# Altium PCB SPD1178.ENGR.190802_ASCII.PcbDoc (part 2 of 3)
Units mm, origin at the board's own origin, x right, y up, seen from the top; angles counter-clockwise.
Board outline 150 x 150 mm, 2 copper layers (Top Layer, Bottom Layer); 315 components, 164 nets, 838 pads, 882 vias.
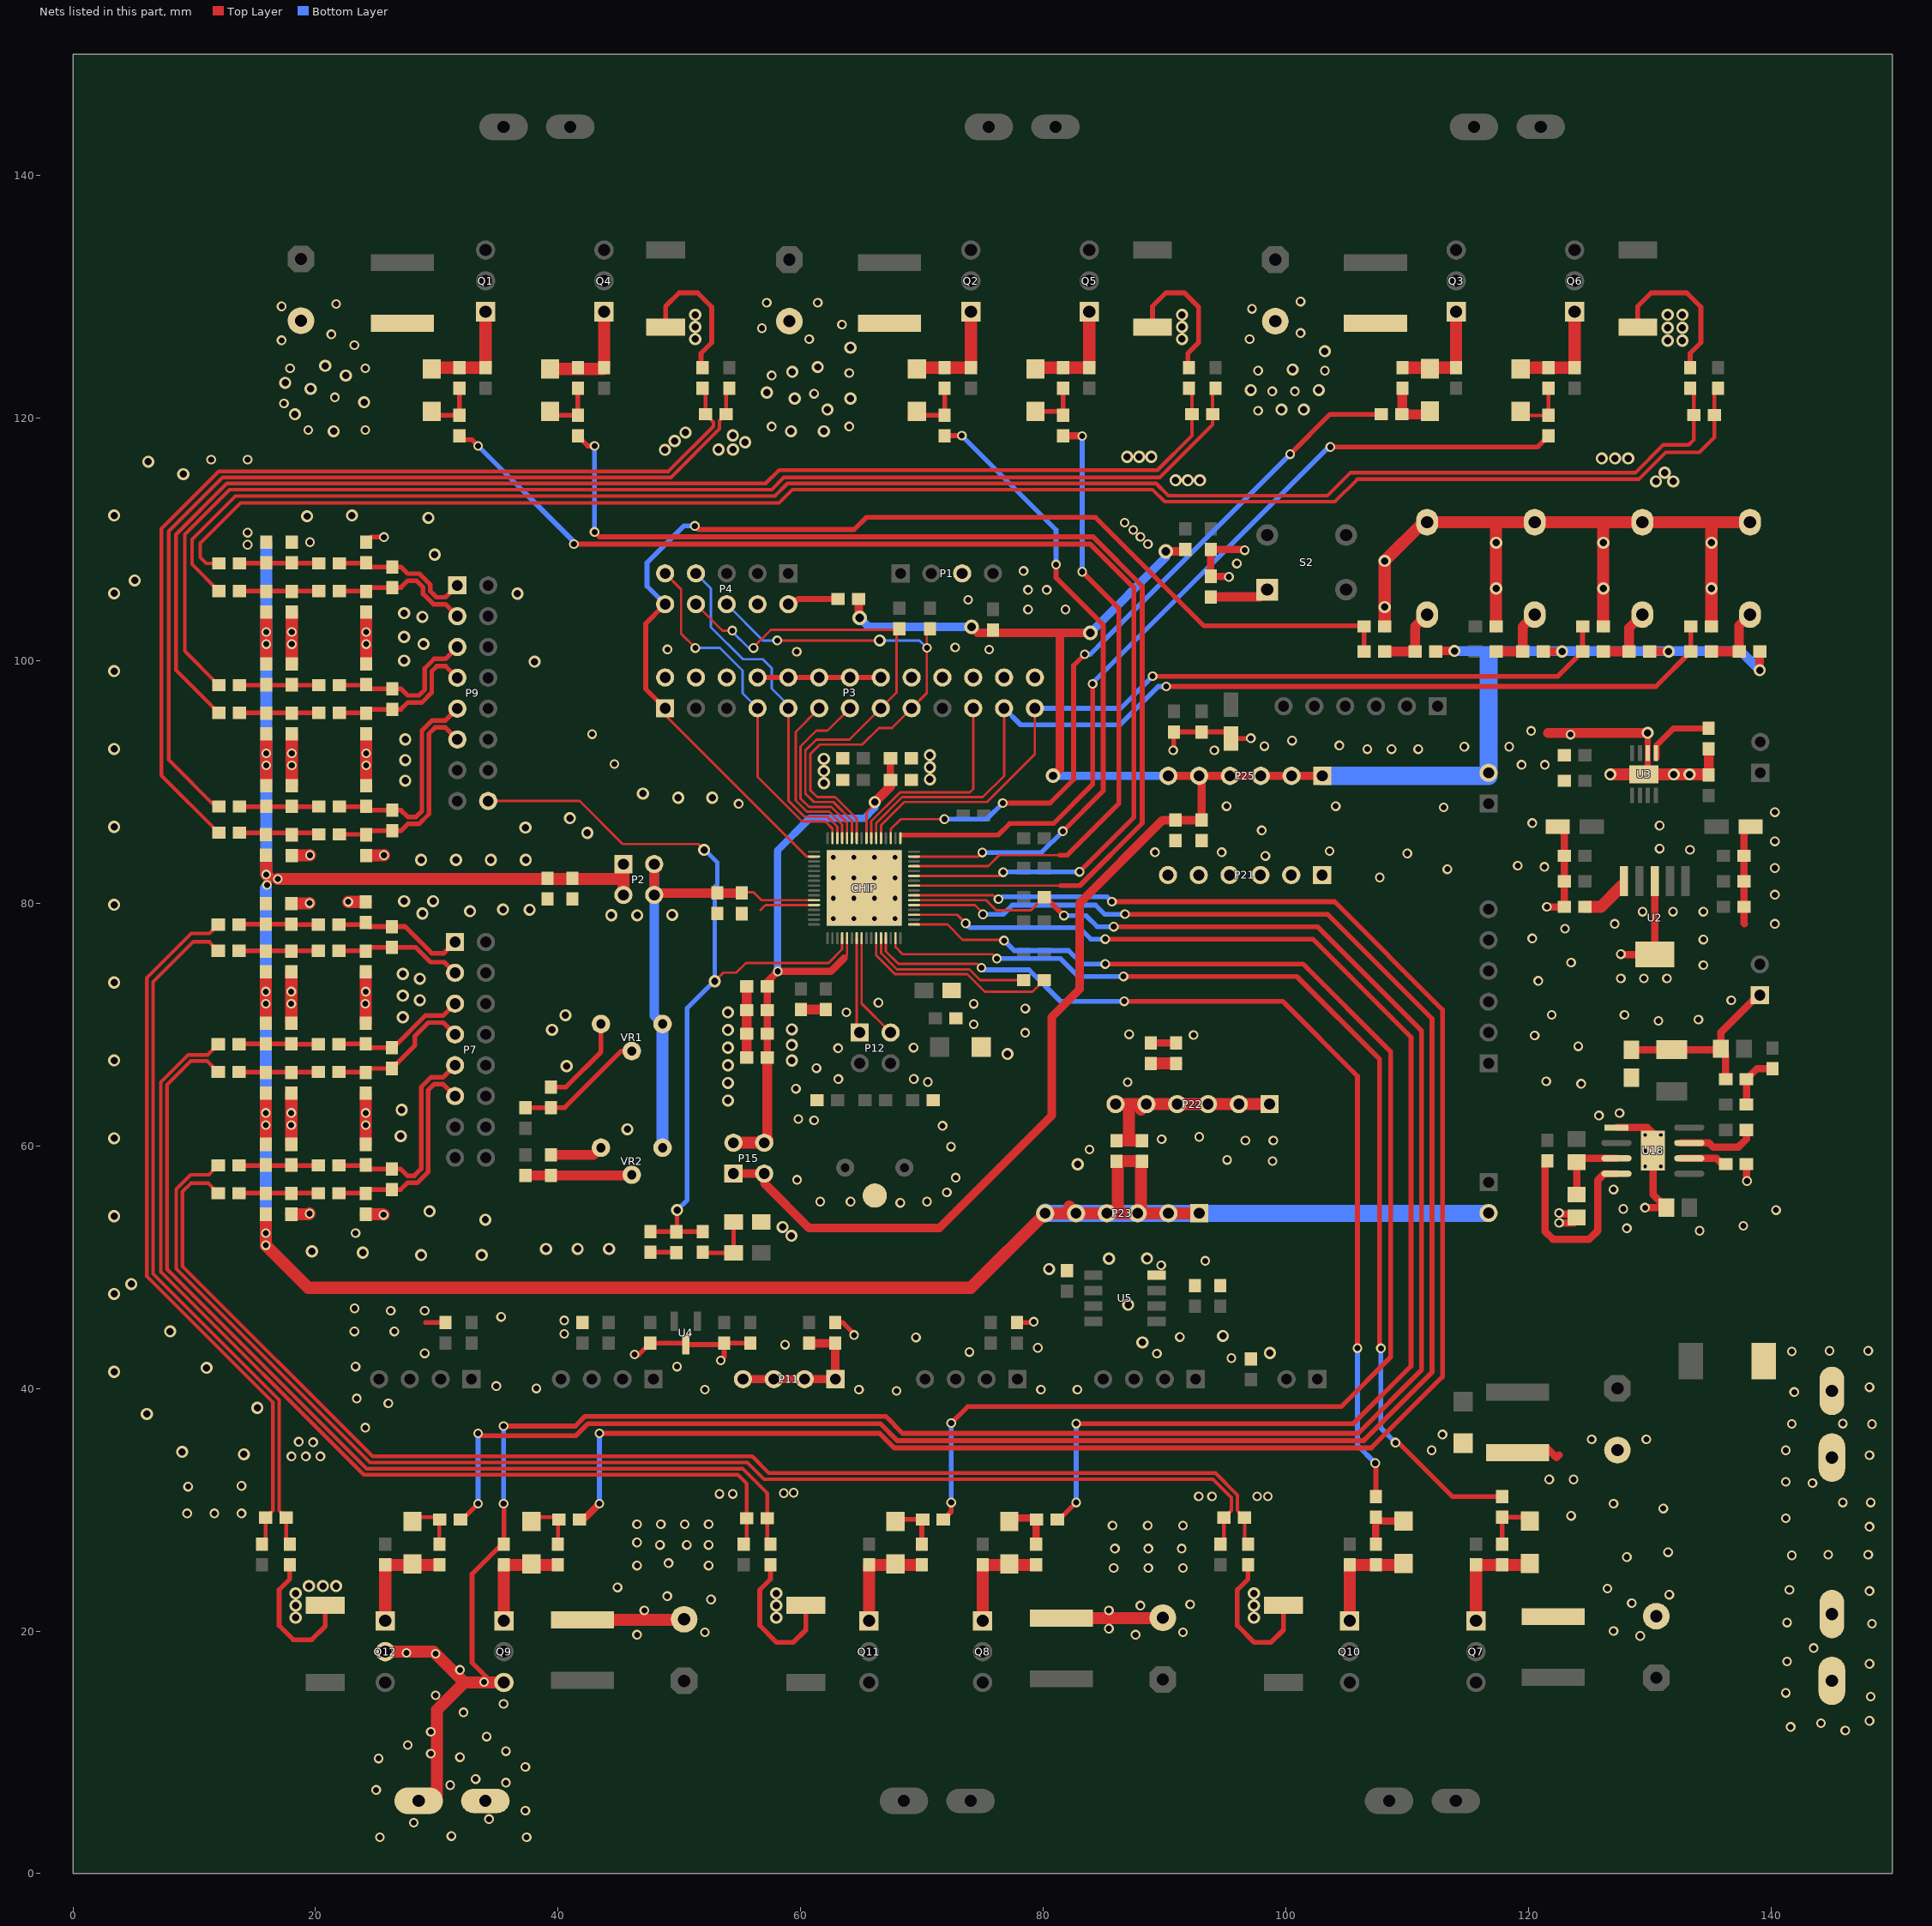
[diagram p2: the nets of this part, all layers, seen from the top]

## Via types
v1: diameter 0.8, hole 0.5, Top Layer to Bottom Layer, tented both sides, 575 vias
v2: diameter 1, hole 0.6, Top Layer to Bottom Layer, 157 vias
v3: diameter 0.8, hole 0.5, Top Layer to Bottom Layer, 69 vias
v4: diameter 1, hole 0.6, Top Layer to Bottom Layer, tented both sides, 52 vias
v5: diameter 0.8, hole 0.4, Top Layer to Bottom Layer, 16 vias
v6: diameter 1.2, hole 0.7, Top Layer to Bottom Layer, tented both sides, 7 vias
v7: diameter 0.5, hole 0.3, Top Layer to Bottom Layer, 6 vias

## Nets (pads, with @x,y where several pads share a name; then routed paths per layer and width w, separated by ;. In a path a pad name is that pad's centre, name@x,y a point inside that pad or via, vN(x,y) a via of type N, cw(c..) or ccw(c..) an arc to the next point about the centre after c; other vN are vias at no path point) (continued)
ADC15: CHIP.20 CL420.2 P9.16 R442.1 R443.1 | length 69.7
  Top Layer w0.2: P9.16@34.232,88.42 41.78,88.42 45.32,84.88 51.55,84.88 v4(52.03,84.4) ; v4(52.91,73.57) 53.62,74.28 54.68,74.28 55.48,75.08 62.29,75.08 63.413,76.203 CHIP.20@63.413,77.117
  Top Layer w0.381: CL420.2@47.608,52.92 R443.1@49.767,52.92 ; v4(49.8,54.7) 49.8,52.953 R443.1@49.767,52.92 ; R442.1@51.926,52.92 R443.1@49.767,52.92
  Bottom Layer w0.381: v4(49.8,54.7) 50.64,55.54 50.64,71.35 v4@52.91,73.62 ; v4(52.03,84.4) 52.08,84.4 53.121,83.359 53.121,81.54 52.91,81.329 v4@52.91,73.62 ; v4(52.91,73.57) v4@52.91,73.62
AGND: C90.1 C91.1 C132.2 C133.2 C142.2 C143.2 C152.2 C153.2 C162.2 C163.2 C172.2 C173.2 C182.2 C183.2 C232.2 C233.1 C234.2 C235.1 C236.2 C237.1 C238.2 C239.1 C240.2 C241.1 C242.2 C243.1 CB8.1 CB9.1 CB10.1 CF3.2 CF4.2 CHIP.12 CL1.1 CL2.1 CL4.2 CL5.2 CL6.2 CL13.1 CL14.1 CL27.1 CL28.1 CL29.1 CL38.1 CL39.1 CL420.1 P22.1 P22.2 P22.3 P22.4 P22.5 P22.6 R41.1 R43.1 R443.2 U4.3 U5.4 VR1.3 VR2.3 | length 100.1
  Top Layer w0.2: 56.67,79.43 57.087,79.847 CHIP.12@61.094,79.847
  Top Layer w0.4: C153.2@24.172,109.756 24.592,110.176 v1(25.642,110.176) ; 29.073,45.427 CL5.2@30.701,45.427 ; C90.1@39.4,64.85 40.65,64.85 43.528,67.728 VR1.3@43.528,70.044 ; v1(46.3,42.8) 46.665,42.8 CB9.1@47.592,43.727 50.403,43.727 U4.3@50.513,43.617 53.578,43.617 CL29.1@53.688,43.727 ; CL420.1@47.608,51.22 R443.2@49.767,51.22 ; v1(53.4,42.3) 53.688,42.588 CL29.1@53.688,43.727 ; CB8.1@55.847,43.727 CL29.1@53.688,43.727 ; CL6.2@62.832,45.427 63.473,45.427 64.4,44.5 v1(64.4,44.4) ; CL4.2@77.818,45.427 79.127,45.427 v1(79.2,45.5)
  Top Layer w0.8: C91.1@39.4,59.25 42.934,59.25 VR2.3@43.528,59.844
  Top Layer w1: C238.2@18.004,54.358 19.45,54.358 v1(19.504,54.412) ; C239.1@18.004,60.122 v1(18.004,61.712) v1(18.004,62.712) C240.2@18.004,64.345 ; C241.1@18.004,70.109 v1(18.004,71.712) v1(18.004,72.712) C242.2@18.004,74.34 ; C243.1@18.029,79.977 19.469,79.977 v1(19.504,80.012) ; C232.2@18.042,83.937 19.519,83.937 v1(19.542,83.96) ; C233.1@18.042,89.701 v1(18.042,91.36) v1(18.042,92.36) C234.2@18.042,93.951 ; C235.1@18.042,99.71 v1(18.042,101.36) v1(18.042,102.36) C236.2@18.042,103.992 ; v1(22.704,80.112) 22.712,80.104 C183.2@24.134,80.104 ; C162.2@24.134,54.358 25.558,54.358 v1(25.604,54.312) ; C163.2@24.134,60.122 v1(24.134,61.712) v1(24.134,62.712) C172.2@24.134,64.345 ; C173.2@24.134,70.109 v1(24.134,72.712) C182.2@24.134,74.34 ; C132.2@24.172,83.937 25.619,83.937 v1(25.642,83.96) ; C133.2@24.172,89.701 v1(24.172,91.36) v1(24.172,92.36) C142.2@24.172,93.951 ; C143.2@24.172,99.715 v1(24.172,101.36) v1(24.172,102.36) C152.2@24.172,103.992 ; P22.6@85.95,63.44 P22.5@88.49,63.44 ; CF4.2@86.03,60.43 87.13,60.43 CF3.2@88.13,60.43 ; 87.05,60.43 87.05,63 ; P22.5@88.05,63 P22.5@88.49,63.44 ; R43.1@88.85,66.79 R41.1@90.95,66.79 ; P22.1@98.65,63.44 P22.2@96.11,63.44 P22.3@93.57,63.44 P22.4@91.03,63.44 P22.5@88.49,63.44
  other v1: 67.9,39.8 52.1,39.9 64.8,39.9 79.8,39.9 82.8,39.9 38.2,40 34.9,40.2 23.3,41.8 49.8,41.8 95.5,42.5 89.36,42.87 29,42.9 73.9,43 79.54,43.35 58.7,43.6 69.5,44.2 91.25,44.24 40.5,44.5 40.5,45.6 35.3,45.9 29,46.4 89.71,50.15 93.35,50.52 23.3,52.8 98.89,58.74 95.15,58.84 83.8,59.69 96.65,60.44 98.95,60.44 89.75,60.54 92.85,60.74 86.95,65.24 24.104,71.712 19.542,109.76
  other v2: 14.1,34.567 9,34.767 6.1,37.9 15.2,38.4 3.4,41.367 11.016,41.7 98.67,42.92 88.17,43.8 94.8,44.33 8.016,44.7 3.4,47.785 4.816,48.6 80.47,49.84 85.41,50.7 88.54,50.71 28.7,51 33.7,51 23.9,51.2 19.7,51.3 39,51.5 41.6,51.5 44.2,51.5 34,53.9 3.4,54.204 29.4,54.6 82.83,58.48 3.4,60.622 27.016,60.8 45.7,61.367 27.1,62.967 40.7,66.567 3.4,67.04 39.5,69.567 27.2,70.6 40.6,70.767 28.6,72 27.2,72.384 3.4,73.458 28.6,73.767 27.2,74.167 46.52,79 44.39,79.01 49.41,79.03 28.81,79.15 32.73,79.34 35.45,79.48 37.65,79.46 3.4,79.876 27.3,80.167 29.7,80.167 28.7,83.567 31.577,83.567 34.453,83.567 37.33,83.567 42.41,85.8 37.3,86.23 3.4,86.295 40.97,87.01 49.9,88.7 52.7,88.7 46.99,89.04 27.4,90.1 27.4,91.8 3.4,92.713 27.4,93.5 3.4,99.131 38.06,99.91 27.3,100 28.9,101.367 27.3,101.95 28.816,103.6 27.3,103.9 36.65,105.52 3.4,105.549 5.1,106.6 29.82,108.74 29.3,111.767 19.3,111.9 3.4,111.967 23,111.967 130.5,114.767 131.92,114.767 90.9,114.867 91.9,114.867 92.9,114.867 9.1,115.367 131.216,115.483 6.216,116.4 126.03,116.66 127.123,116.66 128.216,116.66 86.9,116.8 87.9,116.8 88.9,116.8 48.8,117.367 53.216,117.4 54.416,117.4 55.416,118 49.6,118.1 54.4,118.567 50.5,118.8
  other v3: 9.416,29.7 11.658,29.7 13.9,29.7 92.8,31.1 93.9,31.1 97.616,31.1 98.5,31.1 53.3,31.3 54.4,31.3 58.6,31.367 59.416,31.4 9.5,31.9 13.9,31.967 18.016,34.4 19.2,34.4 20.4,34.4 19.8,35.567 18.616,35.6 24.1,36.767 26,38.767 23.4,39.167 23.2,44.7 26.5,44.7 26.2,46.4 23.216,46.6 54.88,88.19 44.64,91.47 42.8,93.93 11.4,116.567 14.4,116.567
  other v4: 86.99,46.9
ATEST: CL6.1 P11.1 P11.2 P11.3 P11.4 R34.1 | length 12.7
  Top Layer w0.7: P11.4@55.237,40.767 P11.3@57.777,40.767 P11.2@60.317,40.767 P11.1@62.857,40.767 62.832,40.792 CL6.1@62.832,43.727 R34.1@60.673,43.727
AVDD: CHIP.11 CL1.2 CL2.2 P2.2 P2.4 VR1.1 VR2.1 | length 39.9
  Top Layer w0.2: CL1.2@55.063,80.907 56.113,80.907 56.773,80.247 CHIP.11@61.094,80.247
  Top Layer w0.6: P2.2@47.92,83.22 P2.2@48.077,83.063
  Top Layer w0.8: P2.2@48.077,83.063 47.92,82.906 P2.4@47.92,80.68 48.077,80.837 CL1.2@55.133,80.837
  Bottom Layer w0.8: P2.2@47.92,83.22 P2.4@47.92,80.68 47.92,70.732 VR1.1@48.608,70.044
  Bottom Layer w1: VR2.1@48.608,59.844 VR1.1@48.608,70.044
AVDD_3V3: CF3.1 CF4.1 CL27.2 CL28.2 P2.1 P2.3 P23.1 P23.2 P23.3 P23.4 P23.5 P23.6 P27.2 R130.2 R131.2 R140.2 R141.2 R150.2 R151.2 R160.2 R161.2 R170.2 R171.2 R180.2 R181.2 | length 236.3
  Top Layer w1: R160.2@15.904,54.358 15.9,54.354 v1(15.9,51.8) 19.4,48.3 74.01,48.3 P23.6@80.15,54.44 P23.6@80.05,54.54 ; R161.2@15.904,60.122 v1(15.904,61.712) v1(15.904,62.712) R170.2@15.904,64.345 ; R171.2@15.904,70.109 v1(15.904,71.712) v1(15.904,72.712) R180.2@15.904,74.34 ; R130.2@15.942,83.937 v1(15.942,82.36) v1@16.142,82.16 ; R131.2@15.942,89.701 v1(15.942,91.36) v1(15.942,92.36) R140.2@15.942,93.951 ; R141.2@15.942,99.71 v1(15.942,101.36) v1(15.942,102.36) R150.2@15.942,103.992 ; v1(16.9,82) 45.38,82 ; P2.3@45.38,80.68 45.38,82 ; P2.1@45.38,83.22 45.38,82 ; 45.39,82 45.38,82 ; P23.6@80.2,54.44 P23.4@85.23,54.44 ; 82.15,54.98 P23.5@82.69,54.44 ; CF4.1@86.03,58.73 CF3.1@88.13,58.73 ; CF4.1@86.13,58.63 86.13,54.44 P23.3@87.77,54.44 P23.2@90.31,54.44 P23.1@92.85,54.44 ; P23.3@88.05,54.98 CF3.1@88.05,58.73
  Bottom Layer w1: v1(15.9,51.8) 15.904,51.804 v1(15.904,52.8) v1(15.904,61.712) v1@15.904,62.412 ; v1(15.904,62.712) v1(15.904,71.712) v1(15.904,72.712) v1@15.904,81.212 ; v1(15.942,82.36) v1(15.942,91.36) v1(15.942,92.36) v1(15.942,101.36) ; v1@15.942,101.46 v1(15.942,102.36) 15.942,109.65
  Bottom Layer w1.4: P23.6@80.15,54.44 P23.5@82.69,54.44 P23.4@85.23,54.44 P23.3@87.77,54.44 P23.2@90.31,54.44 P23.1@92.85,54.44 116.68,54.44 P27.2@116.7,54.46 ; P23.6@80.15,54.542 P23.6@80.201,54.491
  other v1: 16,81.5 14.4,109.55 14.4,110.55
BUCK_OUT_5V: C54.1 C55.2 L1.2 P17.1 R53.1 | length 15.3
  Top Layer w0.6: C54.1@128.18,67.953 128.204,67.929 L1.2@132.3,67.929 ; L1.2@132.6,67.929 R53.1@135.621,67.929 ; C55.2@136.25,65.8 136.25,67.6 R53.1@135.85,68 135.85,69.35 138.921,72.421 P17.1@139.06,72.421
CFBOT: CHIP.27 CL34.2 | length 16.9
  Top Layer w0.2: CHIP.27@66.213,77.117 66.213,75.706 67.77,74.149 73.731,74.149 75.18,72.7 79.105,72.7 CL34.2@80.065,73.66
CFTOP: CHIP.28 CL34.1 | length 13.9
  Top Layer w0.2: CHIP.28@66.613,77.117 66.613,75.871 67.935,74.549 73.897,74.549 74.786,73.66 CL34.1@78.365,73.66
DVDD: CHIP.21 CHIP.56 CL15.2 CL16.2 CL17.2 CL20.2 CL35.2 CL36.2 P15.2 P15.4 | length 52
  Top Layer w0.2: 63.569,75.471 63.813,75.714 CHIP.21@63.813,77.117 ; CHIP.56@65.413,85.367 65.413,87.513 v4@66.165,88.265
  Top Layer w0.6: CL17.2@57.25,67.28 CL20.2@57.25,69.235 CL36.2@57.25,71.19 CL35.2@57.25,73.145 57.25,73.53 v1(58.1,74.38) 62.479,74.38 63.569,75.471 ; 67.4,89.63 CL16.2@67.4,90.16 CL15.2@67.4,91.95
  Top Layer w0.8: P15.4@57.25,60.51 CL17.2@57.25,67.21 ; v4(66.1,88.33) 67.4,89.63
  Top Layer w1: P15.2@54.45,60.252 56.992,60.252 P15.4@57.25,60.51
  Bottom Layer w0.6: v1(58.1,74.38) 58.1,84.363 60.737,87 65.24,87 66.1,87.86 v4(66.1,88.33)
DVDD_3V3: CF5.1 CF6.1 P15.1 P15.3 P25.1 P25.2 P25.3 P25.4 P25.5 P25.6 P28.2 R32.1 R33.1 R39.1 R62.2 R63.2 R68.2 R77.1 | length 189.8
  Top Layer w0.7: P15.1@54.753,57.712 57.293,57.712 P15.3@57.293,57.405 ; P15.3@56.99,57.71 56.99,56.92 60.67,53.24 71.43,53.24 80.69,62.5 80.69,70.62 82.98,72.91 82.98,80.005 89.828,86.853 CF5.1@90.883,86.853 CF6.1@93.042,86.853 93.042,90.298 P25.5@92.84,90.5 ; R68.2@64.78,105.08 64.78,103.6 v6(64.85,103.53) ; v6(74.08,102.79) 74.59,102.28 R62.2@75.845,102.28 ; R62.2@75.845,102.528 R62.2@75.845,102.28 ; v6(80.8,90.5) 81.36,91.06 81.36,102.19 ; v6(83.86,102.28) R62.2@75.845,102.28 ; v6(90.1,109) 91.55,109 R63.2@91.7,109.15 ; P25.6@90.3,90.5 P25.5@92.84,90.5 ; P25.1@103,90.5 P25.2@100.46,90.5 P25.3@97.92,90.5 P25.4@95.38,90.5 P25.5@92.84,90.5 ; R77.1@112.35,100.75 112.39,100.79 v4(113.89,100.79) ; R32.1@121.21,100.75 v4(122.76,100.75) ; R33.1@129.99,100.75 v4(131.54,100.75) ; v4(139.05,99.2) R39.1@139.05,100.75
  Bottom Layer w0.7: v6(64.85,103.53) 65.59,102.79 v6(74.08,102.79) ; v6(80.8,90.5) P25.6@90.3,90.5 ; v6(83.86,102.28) 90.1,108.52 v6(90.1,109)
  Bottom Layer w0.8: v4(113.89,100.79) 115.3,100.79 137.46,100.79 v4(139.05,99.2)
  Bottom Layer w1.5: P25.1@103,90.5 116.7,90.5 P28.2@116.7,90.75 116.7,100.36
GND: C1.2 C2.2 C3.2 C4.2 C5.2 C6.2 C16.2 C17.2 C18.2 C19.2 C20.2 C21.2 C28.2 C29.2 C30.2 C54.2 C60.1 CB1.2 CB2.2 CB3.2 CB4.2 CB5.2 CB6.2 CB7.2 CF1.2 CF2.2 CF5.2 CF6.2 CHIP.65 CL3.1 CL7.2 CL8.2 CL9.2 CL10.2 CL11.1 CL12.1 CL15.1 CL16.1 CL17.1 CL18.1 CL19.1 CL20.1 CL21.2 CL22.2 CL23.2 CL24.2 CL25.2 CL26.2 CL30.1 CL31.1 CL32.1 CL33.1 CL35.1 CL36.1 CL621.1 GND.1 P1.3 P3.2 P3.4 P3.6 P3.8 P3.10 P3.12 P3.14 P3.16 P3.18 P3.20 P3.22 P3.24 P3.26 P4.4 P21.1 P21.2 P21.3 P21.4 P21.5 P21.6 pad.0 R13.1 R14.1 R15.1 R28.1 R29.1 R30.1 R41.2 R43.2 R54.2 R59.2 R66.1 R134.1 R144.1 R154.1 R164.1 R174.1 R184.1 R441.1 S1.2 S3.2 S4.2 S5.2 U2.3 U2.6 U3.6 U3.9 U18.1 U18.9 | length 256.6
  Top Layer w0.4: R184.1@17.874,25.455 17.874,24.273 16.994,23.393 16.994,20.454 18.157,19.29 19.69,19.29 20.795,20.395 R30.1@20.795,22.114 ; R13.1@48.862,127.492 48.862,129.211 49.967,130.316 51.5,130.316 52.663,129.152 52.663,126.213 51.783,125.333 R134.1@51.783,124.151 ; P3.8@56.438,98.609 P3.10@58.978,98.609 P3.12@61.518,98.609 P3.14@64.058,98.609 P3.16@66.598,98.609 ; R174.1@57.498,25.455 57.498,24.273 ; R174.1@57.5,25.45 57.5,24.275 57.498,24.273 ; R29.1@60.419,22.114 60.419,20.095 59.39,19.066 58.006,19.066 56.618,20.454 56.618,23.393 57.498,24.273 ; R14.1@88.994,127.492 88.994,129.211 90.099,130.316 91.632,130.316 92.795,129.152 92.795,126.213 91.915,125.333 R144.1@91.915,124.151 ; v1(90.7,92.6) 90.756,92.656 CL25.2@90.756,94.118 CL26.2@93.042,94.118 94.905,94.118 CB3.2@95.455,93.568 97.068,93.568 v1(97.1,93.6) ; R164.1@96.868,25.455 96.868,24.273 95.988,23.393 95.988,20.454 97.376,19.066 98.76,19.066 99.789,20.095 R28.1@99.789,22.114 ; R15.1@128.999,127.492 128.999,129.211 130.104,130.316 133.037,130.316 134.2,129.152 134.2,126.213 133.32,125.333 R154.1@133.32,124.151
  Top Layer w0.5: v4(129.81,94.04) 129.81,90.97 U3.9@129.83,90.95
  Top Layer w0.6: R43.2@88.85,68.49 R41.2@90.95,68.49 ; v1(95.3,106.9) 95.25,106.95 R66.1@93.8,106.95 CL3.1@93.8,109.15 96.54,109.15 v1(96.59,109.1) ; C30.2@117.8,35.086 121.514,35.086 122.3,34.3 122.52,34.52 ; v1(121.5,79.7) CB4.2@122.95,79.7 CL23.2@122.95,81.8 CL22.2@122.95,83.9 122.95,85.75 CB1.2@122.4,86.3 ; v1(122.51,53.65) 123.528,53.65 R59.2@123.961,54.083 123.664,54.38 v1@122.514,54.38 ; v1@122.62,53.64 R59.2@123.77,53.64 ; U18.1@127.244,61.51 129.79,61.51 U18.9@130.3,61 ; v1(127.6,75.8) 127.625,75.775 U2.6@130.4,75.775 U2.3@130.4,81.825 ; v1(129.6,54.9) R54.2@131.35,54.9 130.244,56.006 U18.9@130.244,59.61 ; 137.8,78.3 137.75,78.35 CB5.2@137.75,79.7 CF1.2@137.75,81.8 CL21.2@137.75,83.9 137.75,85.75 CB2.2@138.3,86.3 ; C60.1@137.95,58.5 137.95,57.15 v1(138,57.1)
  Top Layer w0.8: CL17.1@55.55,67.28 CL20.1@55.55,69.235 CL36.1@55.55,71.19 CL35.1@55.55,73.145 ; R441.1@56.752,53.721 R441.1@56.963,53.51 ; CL12.1@60.02,71.24 CL11.1@62.07,71.24 ; 121.61,94.04 v4(129.81,94.04) ; CL24.2@134.85,90.71 CB7.2@134.85,92.71
  Top Layer w1: C21.2@42.004,20.931 50.346,20.931 C18.2@50.386,20.971 ; C20.2@81.471,21.058 89.813,21.058 C17.2@89.853,21.098 ; CL7.2@108.14,102.81 v4(108.14,108.22) 111.33,111.41 S1.2@111.63,111.41 S3.2@120.503,111.41 S4.2@129.377,111.41 S5.2@138.25,111.41 ; CL8.2@117.31,102.81 117.31,111.4 ; CL9.2@126.15,102.81 126.15,111.4 ; v4(126.74,90.62) U3.9@129.5,90.62 v4(131.97,90.62) v4(133.27,90.62) CL24.2@134.79,90.62 ; CL10.2@135.07,102.81 135.07,111.4
  other v1: 146.1,11.8 141.6,12.1 144.1,12.4 148.1,12.6 148.2,14.6 141.2,14.9 148.1,17.3 141.3,17.5 143.5,18.6 129.2,19.6 46.5,19.7 87.6,19.7 52.1,19.9 91.5,19.9 127,20 85.4,20.2 148.3,20.6 141.3,20.7 47.1,21.7 85.4,21.7 88,22.1 92.1,22.2 128.5,22.3 52.6,22.6 49,22.876 131.6,23 148.1,23.3 141.5,23.4 126.5,23.5 44.9,23.6 85.8,25.2 91.5,25.2 46.5,25.4 52.4,25.4 128.1,26.1 141.698,26.244 144.7,26.3 148,26.3 131.5,26.5 88.6,28.7 48.467,28.8 123.5,29.5 131.1,30.1 127,30.5 121.7,32.5 123.7,32.5 112,34.9 125.2,35.8 129.7,35.8 112.9,36.2 134.1,53 128.1,53.2 137.7,53.4 122.51,54.47 140.4,54.7 127.8,54.8 68.2,55.3 61.6,55.4 64.1,55.4 70.4,55.4 72.04,56.16 127,56.4 59.7,57.2 72.77,57.37 72.39,59.93 71.69,61.65 61.1,62.1 59.8,62.2 125.8,62.5 127.5,62.7 59.6,64.7 124.33,65.11 70.47,65.26 121.45,65.32 63.1,65.5 69.32,65.51 61.3,66.4 63.08,68.05 69.3,68.1 124.1,68.2 120.5,69.1 92.38,69.13 87.07,69.19 78.5,69.32 74.26,70.02 130.7,70.3 134,70.4 121.9,70.8 127.9,70.8 63.76,71.01 78.51,71.31 74.26,71.7 66.4,71.8 136.7,72 120.8,73.6 127.6,73.8 129.5,73.8 131.4,73.8 134.4,74.9 123.5,75.1 134.4,77 120.3,77.1 123,77.9 127.1,78.3 140.3,78.3 129.4,79.3 131.9,79.3 134.4,79.3 140.3,80.7 107.73,82.12 113.3,82.8 140.3,82.9 121.3,83 119.1,83.1 98.3,83.9 110,84.1 89.2,84.2 94.7,84.2 103.6,84.3 133.3,84.4 130.8,84.5 140.3,85.1 98,86 130.8,86.4 120.3,86.6 140.3,87.5 113,87.9 95.1,88 104.1,88 119.42,91.41 121.34,91.41 106.7,92.7 108.7,92.7 110.9,92.7 114.7,92.9 118.4,92.9 104.4,93 100.5,93.4 123.46,93.9 120.2,94.2 19.4,119 24.1,119 57.6,119.3 64,119.3 97.7,120.6 17.4,121.2 21.6,121.7 61.1,122 98.867,122.2 100.733,122.2 57.6,123.5 64,123.7 97.7,123.9 103.2,123.9 17.9,124.1 24.1,124.1 23.2,126 17.2,126.4 60.7,126.5 97,126.5 21.3,126.9 101.2,127 56.8,127.4 63.4,127.7 97.2,129 17.2,129.2 21.7,129.4 57.2,129.5 61.4,129.5 101.2,129.6
  other v2: 18.357,21.106 57.981,21.106 97.351,21.106 19.457,23.706 20.616,23.706 21.7,23.706 59.23,52.58 58.5,53.31 54,63.73 54,65.184 54,66.638 59.27,67.03 54,68.092 59.27,68.315 54,69.546 59.27,69.6 54,71 61.9,89.9 70.65,90.21 61.9,90.9 70.65,91.21 61.9,91.9 70.65,92.21 21.5,118.9 59.2,118.9 61.9,118.9 18.3,120.3 62.2,120.7 99.633,120.7 101.467,120.7 24,121.3 59.5,121.6 64.1,121.6 57.2,122.1 97.1,122.3 102.7,122.3 19.6,122.4 17.5,122.9 22.5,123.5 59.3,123.8 100.55,124 61.4,124.2 20.8,124.3 103.2,125.5 64.1,125.8 51.3,128.5 91.432,128.5 131.46,128.5 132.68,128.5
  other v3: 88.65,25.2 49.1,25.6 85.9,26.8 88.65,26.8 91.4,26.8 48.4,27.1 50.6,27.1 52.4,27.1 46.5,27.3 85.7,28.7 91.5,28.7 46.5,28.8 50.433,28.8 52.4,28.8 94.1,92.6 98.22,92.94 59.67,100.73 49.01,100.92 75.53,100.91 72.73,101.08 78.74,104.21 81.82,104.21 73.8,105.01 78.74,105.835 80.28,105.835 78.37,107.39 95.945,108 88.616,109.6 88,110.2 87.4,110.767 86.7,111.367
  other v4: 18.357,22.106 57.981,22.106 97.351,22.106 18.357,23.106 57.981,23.106 97.351,23.106 77.04,67.57 108.14,104.41 117.32,105.94 126.16,105.94 135.08,105.94 117.32,109.72 126.16,109.72 135.08,109.72 131.46,126.37 132.68,126.37 51.3,126.5 91.432,126.5 131.46,127.435 132.68,127.435 51.3,127.5 91.432,127.5
  other v5: 62.694,78.717 64.384,78.717 66.074,78.717 67.764,78.717 62.694,80.407 64.384,80.407 66.074,80.407 67.764,80.407 62.694,82.097 64.384,82.097 66.074,82.097 67.764,82.097 62.694,83.787 64.384,83.787 66.074,83.787 67.764,83.787
  other v7: 129.6,58.3 130.9,58.3 129.6,59.6 130.9,59.6 129.6,60.9 130.9,60.9
GPIO16: CHIP.23 P12.1 | length 7.9
  Top Layer w0.2: CHIP.23@64.613,77.117 64.613,69.593 P12.1@64.864,69.342
GPIO17: CHIP.24 P12.2 | length 8.8
  Top Layer w0.2: CHIP.24@65.013,77.117 65.013,71.733 P12.2@67.404,69.342
GPIO30: CHIP.53 CL9.1 P3.25 R37.1 | length 69.1
  Top Layer w0.2: CHIP.53@66.613,85.367 66.613,86.43 68.523,88.34 75.36,88.34 79.298,92.278 P3.25@79.298,96.069
  Top Layer w0.4: v1(89.01,98.71) 122.41,98.71 R37.1@124.45,100.75 CL9.1@124.45,102.81
  Bottom Layer w0.4: P3.25@79.298,96.069 86.369,96.069 v1(89.01,98.71)
GPIO31: CHIP.54 CL10.1 P3.23 R38.1 | length 80.7
  Top Layer w0.2: CHIP.54@66.213,85.367 66.213,86.596 68.358,88.74 75.01,88.74 76.758,90.488 P3.23@76.758,96.069
  Top Layer w0.4: v1(90.13,97.87) 130.49,97.87 R38.1@133.37,100.75 CL10.1@133.37,102.81
  Bottom Layer w0.4: P3.23@76.758,96.069 78.127,94.7 86.3,94.7 89.47,97.87 v1(90.13,97.87)
GPIO32: CHIP.55 P3.21 | length 17.6
  Top Layer w0.2: CHIP.55@65.813,85.367 65.813,86.761 68.192,89.14 73.94,89.14 74.218,89.418 P3.21@74.218,96.069
GPIO34: CHIP.58 P3.17 P4.6 R75.1 | length 44.4
  Top Layer w0.2: v3(58.06,101.66) v2(66.51,101.66) ; CHIP.58@64.613,85.367 64.613,86.975 62.848,88.74 61.36,88.74 60.8,89.3 60.8,92.3 61.58,93.08 65.08,93.08 66.45,94.45 67.519,94.45 P3.17@69.138,96.069 70.39,97.321 70.39,102.153 R75.1@70.765,102.528
  Bottom Layer w0.2: P4.6@53.898,104.648 56.886,101.66 v3(58.06,101.66) ; v2(66.51,101.66) 69.79,101.66 v3(70.4,101.05)
GPIO35: CHIP.59 P3.15 P4.8 R64.1 | length 43.6
  Top Layer w0.2: P4.8@51.358,104.648 53.536,102.47 v1(54.36,102.47) ; v3(56.11,101.04) 56.11,101.11 57.528,102.528 68.225,102.528 67.89,102.193 67.89,97.361 P3.15@66.598,96.069 64.009,93.48 61.28,93.48 60.39,92.59 60.39,89.04 61.09,88.34 62.683,88.34 64.213,86.81 CHIP.59@64.213,85.367
  Bottom Layer w0.2: v1(54.36,102.47) 54.36,102.371 55.691,101.04 v3(56.11,101.04)
GPIO36: CHIP.60 P3.13 | length 15.6
  Top Layer w0.2: CHIP.60@63.813,85.367 63.813,86.206 63.813,86.644 62.517,87.94 60.68,87.94 59.99,88.63 59.99,92.92 61.29,94.22 62.209,94.22 P3.13@64.058,96.069
GPIO37: CHIP.61 P3.11 | length 14.2
  Top Layer w0.2: P3.11@61.518,96.069 59.58,94.131 59.58,88.46 60.5,87.54 62.351,87.54 63.413,86.478 CHIP.61@63.413,85.367
GPIO38: CHIP.62 P3.9 P4.7 | length 28.7
  Top Layer w0.2: P3.9@58.978,96.069 58.978,88.452 60.29,87.14 62.186,87.14 63.013,86.312 CHIP.62@63.013,85.367
  Bottom Layer w0.2: P4.7@51.358,107.188 52.6,105.946 52.6,102.74 55.23,100.11 56.86,100.11 57.6,99.37 57.6,97.7 58.978,96.322 P3.9@58.978,96.069
GPIO39: CHIP.63 P3.7 P4.9 | length 29.8
  Top Layer w0.2: P4.9@48.818,107.188 50.13,105.876 50.13,102.22 v3(51.31,101.04) ; P3.7@56.438,96.069 56.438,90.408 60.116,86.73 62.03,86.73 62.613,86.147 CHIP.63@62.613,85.367
  Bottom Layer w0.2: v3(51.31,101.04) 53.33,101.04 55.2,99.17 55.2,97.307 P3.7@56.438,96.069
GPIO40: CHIP.2 CL7.1 P3.1 P4.10 R61.1 | length 98.9
  Top Layer w0.2: P3.1@48.818,96.069 48.818,95.522 60.493,83.847 CHIP.2@61.094,83.847
  Top Layer w0.4: P3.1@48.818,96.069 47.22,97.667 47.22,103.05 P4.10@48.818,104.648 P4.10@48.818,104.888 ; v1(51.268,111.1) 51.568,110.8 64.4,110.8 65.4,111.8 84.3,111.8 93.24,102.86 CL7.1@106.7,102.86 ; CL7.1@106.39,102.86 CL7.1@106.44,102.81 ; R61.1@106.44,100.75 106.44,101.42 CL7.1@106.44,102.86
  Bottom Layer w0.4: P4.10@48.818,104.648 47.33,106.136 47.33,108.06 50.37,111.1 v1(51.268,111.1)
HO0_U: CHIP.39 R20.1 | length 158.3
  Top Layer w0.2: CHIP.39@69.333,80.647 75.853,80.647 76.16,80.34 v1(76.3,80.34)
  Top Layer w0.4: R20.1@41.75,29.3 R20.1@42.2,29.3 ; v1(43.4,36.3) 66.5,36.3 67.7,35.1 107.033,35.1 112.9,40.967 112.9,71.23 104.01,80.12 v1(85.65,80.12)
  Top Layer w0.6: R20.1@42.2,29.3 v1(43.4,30.5)
  Bottom Layer w0.4: v1(43.4,30.5) v1(43.4,36.3) ; v1(76.3,80.34) 76.44,80.34 76.63,80.53 85.24,80.53 v1(85.65,80.12)
HO0_V: CHIP.35 R18.1 | length 110.4
  Top Layer w0.2: CHIP.35@69.333,79.047 72.893,79.047 v1(73.6,78.34)
  Top Layer w0.4: R18.1@81.15,29.3 81.4,29.3 v1(82.7,30.6) ; v1(82.7,37.1) 105.56,37.1 110.309,41.849 110.309,68.951 102.219,77.041 v1(85.1,77.041)
  Bottom Layer w0.4: v1(73.6,78.34) 73.95,77.99 82.96,77.99 83.909,77.041 v1(85.1,77.041) ; v1(82.7,30.6) v1(82.7,37.1)
HO0_W: CHIP.31 R16.1 | length 87.5
  Top Layer w0.2: CHIP.31@67.813,77.117 67.813,76.369 68.381,75.8 75.805,75.8 v1(76.167,75.438)
  Top Layer w0.4: v1(86.6,73.962) 100.888,73.962 107.718,67.132 v1@107.718,43.412 ; v1(109.03,35.53) 109.03,35.77 113.708,31.092 R16.1@117.823,31.092
  Bottom Layer w0.4: v1(76.167,75.438) 81.402,75.438 82.878,73.962 v1(86.6,73.962) ; v1(107.82,43.31) 107.82,36.74 v1(109.03,35.53)
HO1_U: CHIP.51 R5.1 | length 60.9
  Top Layer w0.2: CHIP.51@67.413,85.367 67.413,86.099 68.245,86.93 v1(71.84,86.93)
  Top Layer w0.4: v3(76.65,88.25) 80.55,88.25 82.49,90.19 82.49,99.6 v1(83.41,100.52) ; v3(100.34,117.01) 103.63,120.3 R5.1@107.85,120.3
  Bottom Layer w0.4: v1(71.84,86.93) 75.33,86.93 v3(76.65,88.25) ; v1(83.41,100.52) 83.86,100.52 85.045,101.705 v3@100.345,117.005 ; v3@100.34,117 v3(100.34,117.01)
HO1_V: CHIP.47 R3.1 | length 53.4
  Top Layer w0.2: CHIP.47@69.333,83.847 74.627,83.847 v1(74.96,84.18)
  Top Layer w0.4: R3.1@71.865,118.514 71.891,118.54 v1(73.28,118.54) ; v1(81.04,107.92) 81.04,106.829 84.93,102.939 84.93,89.26 v1(81.6,85.93)
  Bottom Layer w0.4: v1(73.28,118.54) 81.04,110.78 v1(81.04,107.92) ; v1(74.96,84.18) 79.85,84.18 v1(81.6,85.93)
HO1_W: CHIP.43 R1.1 | length 99.9
  Top Layer w0.2: CHIP.43@69.333,82.247 76.387,82.247 v1(76.69,82.55)
  Top Layer w0.4: R1.1@31.86,118.514 32.174,118.2 32.9,118.2 v1(33.4,117.7) ; v1(41.3,109.6) 83.851,109.6 87.47,105.981 87.47,87.08 v1(82.978,82.588)
  Bottom Layer w0.4: v1(33.4,117.7) 41.3,109.8 v1(41.3,109.6) ; v1@76.69,82.588 v1(82.978,82.588)
LO0_U: CHIP.37 R26.1 | length 166.3
  Top Layer w0.2: CHIP.37@69.333,79.847 74.353,79.847 75.02,79.18 v1(75.02,79.08)
  Top Layer w0.4: R26.1@31.95,29.2 32.1,29.2 v1(33.4,30.5) ; v1(33.4,36.3) 33.6,36.1 41.469,36.1 42.469,37.1 66.549,37.1 67.949,35.7 106.4,35.7 112.036,41.336 112.036,70.484 103.426,79.094 v1(86.724,79.094)
  Bottom Layer w0.4: v1(33.4,30.5) v1(33.4,36.3) ; v1(75.02,79.08) 76.68,79.08 77.44,79.84 84.3,79.84 85.046,79.094 v1(86.724,79.094)
LO0_V: CHIP.33 R24.1 | length 115.4
  Top Layer w0.2: CHIP.33@69.333,78.247 72.093,78.247 73.35,76.99 v1@76.71,76.99
  Top Layer w0.4: R24.1@71.75,29.2 72.4,29.85 v1(72.4,30.6) ; v1(72.4,37.146) 73.754,38.5 104.553,38.5 108.62,42.567 108.62,67.77 101.401,74.989 v1(85.1,74.989)
  Bottom Layer w0.4: v1(72.4,30.6) v1(72.4,37.146) ; v1(76.76,76.92) 76.78,76.92 77.6,76.1 82.08,76.1 83.191,74.989 v1(85.1,74.989)
LO0_W: CHIP.29 R22.1 | length 79.4
  Top Layer w0.2: CHIP.29@67.013,77.117 67.013,76.037 68.05,75 74.573,75 v1(74.897,74.676)
  Top Layer w0.4: v1(86.67,71.91) 99.73,71.91 105.89,65.75 v1(105.89,43.32) ; R22.1@107.409,31.092 v1@107.409,33.791
  Bottom Layer w0.4: v1(74.897,74.676) 75.073,74.5 78.82,74.5 81.41,71.91 v1(86.67,71.91) ; v1(105.89,43.32) 105.89,35.31 v1(107.36,33.84)
LO1_U: CHIP.49 R11.1 | length 71.8
  Top Layer w0.4: 68.33,85.63 76.29,85.63 77.23,86.57 80.84,86.57 84.06,89.79 v1(84.06,98.08) ; v3(103.65,117.61) 120.729,117.61 R11.1@121.633,118.514
  Bottom Layer w0.4: v1(84.06,98.08) 84.06,98.147 103.523,117.61 v3(103.65,117.61)
LO1_V: CHIP.45 R9.1 | length 52.2
  Top Layer w0.2: CHIP.45@69.333,83.047 75.447,83.047 76.36,83.96 81.34,83.96
  Top Layer w0.4: 81.34,83.96 81.97,83.96 86.22,88.21 86.22,104.3 v1(83.2,107.32)
  Top Layer w0.6: R9.1@81.628,118.514 81.632,118.51 v1(83.2,118.51)
  Bottom Layer w0.4: v1(83.2,107.32) v1(83.2,118.51)
LO1_W: CHIP.41 R7.1 | length 96.3
  Top Layer w0.2: CHIP.41@69.333,81.447 81.43,81.447
  Top Layer w0.4: R7.1@41.623,118.514 42.437,117.7 v1(43,117.7) ; v1(43,110.6) 43.4,110.2 84.1,110.2 88.153,106.147 88.153,86.593 83.007,81.447 81.43,81.447
  Bottom Layer w0.4: v1(43,110.6) v1(43,117.7)
NetC55_1: C55.1 C56.1 R52.1 | length 4.6
  Top Layer w0.6: R52.1@137.95,63.4 C55.1@137.95,65.5 138.8,66.35 C56.1@140.1,66.35
NetC59_1: C59.1 U18.7 | length 6.6
  Top Layer w0.6: U18.7@132.544,60.24 U18.7@133.244,60.24 134.86,60.24 135.2,59.9 137.3,59.9 137.95,60.55 C59.1@137.95,61.3
NetC60_2: C60.2 U18.6 | length 3.6
  Top Layer w0.6: U18.6@132.544,58.97 U18.6@133.244,58.97 135.48,58.97 C60.2@135.95,58.5
NetC71_1: C71.1 D1.1 Q1.1 R2.2 | length 9.1
  Top Layer w1: D1.1@29.574,124.043 29.682,124.151 C71.1@34.019,124.151 Q1.1@34.019,128.762
NetC72_1: C72.1 D4.1 Q4.1 R8.2 | length 13.6
  Top Layer w0.4: D4.1@39.337,124.043 39.445,124.151 R8.2@41.623,124.151 C72.1@43.782,124.151
  Top Layer w1: D4.1@39.337,124.043 43.674,124.043 C72.1@43.782,124.151 Q4.1@43.782,128.762
NetC73_1: C73.1 D5.1 Q5.1 R10.2 | length 9.1
  Top Layer w1: D5.1@79.342,124.043 79.45,124.151 R10.2@81.628,124.151 C73.1@83.787,124.151 Q5.1@83.787,128.762
NetC74_1: C74.1 D2.1 Q2.1 R4.2 | length 9.1
  Top Layer w0.4: D2.1@69.579,124.043 D2.1@69.687,124.151
  Top Layer w1: D2.1@69.687,124.151 R4.2@71.865,124.151 C74.1@74.024,124.151 Q2.1@74.024,128.762
NetC75_1: C75.1 D3.1 Q3.1 R6.2 | length 8.9
  Top Layer w1: R6.2@109.692,124.151 R6.2@109.7,124.151 ; R6.2@109.7,124.15 114.028,124.15 C75.1@114.029,124.151 Q3.1@114.029,128.762
NetC76_1: C76.1 D6.1 Q6.1 R12.2 | length 9.1
  Top Layer w0.3: D6.1@119.347,124.043 D6.1@119.455,124.151
  Top Layer w1: D6.1@119.455,124.151 R12.2@121.633,124.151 C76.1@123.792,124.151 Q6.1@123.792,128.762
NetC77_1: C77.1 D7.1 Q7.1 R17.2 | length 9.1
  Top Layer w0.4: D7.1@120.001,25.455 D7.1@120.109,25.563
  Top Layer w1: Q7.1@115.664,20.844 C77.1@115.664,25.455 R17.2@117.823,25.455 D7.1@120.001,25.455
NetC78_1: C78.1 D10.1 Q10.1 R23.2 | length 9.1
  Top Layer w0.4: D10.1@109.587,25.455 D10.1@109.695,25.563
  Top Layer w1: Q10.1@105.25,20.844 C78.1@105.25,25.455 R23.2@107.409,25.455 D10.1@109.587,25.455
NetC79_1: C79.1 D8.1 Q8.1 R19.2 | length 9.1
  Top Layer w0.4: R19.2@79.331,25.455 R19.2@79.439,25.563
  Top Layer w1: Q8.1@74.994,20.844 C79.1@74.994,25.455 77.153,25.455 R19.2@79.331,25.455
NetC80_1: C80.1 D11.1 Q11.1 R25.2 | length 9.1
  Top Layer w0.4: 69.163,25.455 69.271,25.563
  Top Layer w1: Q11.1@65.626,20.844 C80.1@65.626,25.455 67.785,25.455 R25.2@69.963,25.455
NetC81_1: C81.1 D9.1 Q9.1 R21.2 | length 9.1
  Top Layer w0.305: R21.2@39.864,25.455 R21.2@39.972,25.563
  Top Layer w1: Q9.1@35.527,20.844 C81.1@35.527,25.455 37.686,25.455 R21.2@39.864,25.455
NetC82_1: C82.1 D12.1 Q12.1 R27.2 | length 9.1
  Top Layer w0.305: R27.2@30.385,25.455 R27.2@30.493,25.563
  Top Layer w1: Q12.1@25.748,20.844 C82.1@25.748,25.455 27.907,25.455 R27.2@30.085,25.455
NetC90_2: C90.2 R93.1 VR1.2 | length 10.7
  Top Layer w0.381: R93.1@37.3,63.05 37.4,63.15 C90.2@39.4,63.15 40.55,63.15 45.214,67.814 VR1.2@46.068,67.814
NetC91_2: C91.2 R94.1 VR2.2 | length 8.8
  Top Layer w0.381: VR2.2@45.904,57.55 45.954,57.5 VR2.2@46.068,57.614
  Top Layer w0.8: R94.1@37.3,57.55 C91.2@39.4,57.55 VR2.2@45.904,57.55
NetC130_1: C130.1 R133.1 R135.2 | length 77.3
  Top Layer w0.3: R133.1@12.019,87.962 11.887,87.829 7.9,91.816 7.9,110.667 12.333,115.1 49.3,115.1 53.3,119.1 53.3,119.75 C130.1@53.85,120.3 53.85,122.2 R135.2@54.1,122.45
NetC130_2: C130.2 R132.1 R134.2 | length 79.6
  Top Layer w0.3: R132.1@11.956,85.74 R132.1@12.019,85.676 ; R132.1@12.019,85.803 7.3,90.522 7.3,110.867 12.033,115.6 49.093,115.6 52.8,119.307 52.8,119.65 C130.2@52.15,120.3 52.15,122.2 R134.2@51.9,122.45
NetC131_1: C131.1 C133.1 P9.9 R137.2 | length 17.7
  Top Layer w0.381: R137.2@21.974,87.962 24.133,87.962 C133.1@24.172,88.001 24.504,87.669 C131.1@26.331,87.669 27.053,87.669 27.613,87.11 28.288,87.11 28.771,87.593 28.771,94.212 29.62,95.061 30.713,95.061 P9.9@31.692,96.04
NetC131_2: C131.2 C132.1 P9.11 R136.2 | length 17.7
  Top Layer w0.381: R136.2@21.974,85.676 24.133,85.676 C132.1@24.172,85.637 24.504,85.969 C131.2@26.331,85.969 27.053,85.969 27.613,86.529 28.529,86.529 29.352,87.352 29.352,93.971 29.86,94.48 30.713,94.48 P9.11@31.692,93.5
NetC140_1: C140.1 R143.1 R145.2 | length 105.2
  Top Layer w0.3: R143.1@12.019,97.976 9.216,100.78 9.216,110.4 12.916,114.1 57.6,114.1 58.6,115.1 89.6,115.1 93.95,119.45 C140.1@93.95,120.3 93.95,122.2 R145.2@94.2,122.45
NetC140_2: C140.2 R142.1 R144.2 | length 107.3
  Top Layer w0.3: R142.1@12.019,95.69 8.5,99.209 8.5,110.4 12.7,114.6 57.1,114.6 58.2,115.7 89.4,115.7 92.25,118.55 C140.2@92.25,120.3 92.25,122.2 R144.2@92,122.45
NetC141_1: C141.1 C143.1 P9.5 R147.2 | length 12.8
  Top Layer w0.381: R147.2@21.974,97.976 24.133,97.976 C143.1@24.172,98.015 24.504,97.683 C141.1@26.331,97.683 27.053,97.683 27.613,97.124 28.524,97.124 29,97.6 29,99.364 29.776,100.141 30.713,100.141 P9.5@31.692,101.12
NetC141_2: C141.2 C142.1 P9.7 R146.2 | length 12.8
  Top Layer w0.381: R146.2@21.974,95.69 24.133,95.69 C142.1@24.172,95.651 24.504,95.983 C141.2@26.331,95.983 27.053,95.983 27.613,96.543 28.764,96.543 29.581,97.359 29.581,99.124 30,99.543 30.73,99.543 P9.7@31.692,98.58
NetC150_1: C150.1 R153.1 R155.2 | length 136.3
  Top Layer w0.3: R153.1@12.019,108.017 10.983,108.017 10.5,108.5 10.5,109.684 13.816,113 58.2,113 59.3,114.1 89,114.1 90,113.1 104.03,113.1 105.88,114.95 129.08,114.95 131.3,117.17 134.08,117.17 135.313,118.403 C150.1@135.313,120.253 135.313,122.158 R155.2@135.606,122.451
NetC150_2: C150.2 R152.1 R154.2 | length 137.6
  Top Layer w0.3: R152.1@12.019,105.731 9.816,107.935 9.816,110 13.383,113.567 57.867,113.567 58.9,114.6 89.3,114.6 90.3,113.6 103.41,113.6 105.29,115.48 128.79,115.48 131.09,117.78 133.19,117.78 133.613,118.203 C150.2@133.613,120.253 133.613,122.158 R154.2@133.32,122.451
NetC151_1: C151.1 C153.1 P9.1 R157.2 | length 11.6
  Top Layer w0.381: R157.2@21.974,108.017 24.133,108.017 C153.1@24.172,108.056 24.504,107.724 C151.1@26.331,107.724 27.053,107.724 27.613,107.165 28.557,107.165 29.449,106.272 29.449,105.735 29.964,105.221 30.713,105.221 P9.1@31.692,106.2
NetC151_2: C151.2 C152.1 P9.3 R156.2 | length 11.6
  Top Layer w0.381: R156.2@21.974,105.731 24.133,105.731 C152.1@24.172,105.692 24.504,106.024 C151.2@26.331,106.024 27.053,106.024 27.613,106.584 28.316,106.584 28.868,106.032 28.868,105.494 29.723,104.64 30.713,104.64 P9.3@31.692,103.66
NetC160_1: C160.1 R163.1 R165.2 | length 109.8
  Top Layer w0.305: R163.1@11.981,58.383 11.21,57.612 9.704,57.612 8.516,56.424 8.516,49.87 24.491,33.895 55.605,33.895 56.978,32.522 93.978,32.522 95.495,31.005 95.495,29.957 C160.1@94.891,29.353 94.891,27.448 R165.2@94.598,27.155
NetC160_2: C160.2 R162.1 R164.2 | length 108.9
  Top Layer w0.305: R162.1@11.981,56.097 11.166,56.912 9.718,56.912 9.021,56.215 9.021,50.079 24.7,34.4 56,34.4 57.373,33.027 94.187,33.027 96,31.214 96,29.944 C160.2@96.591,29.353 96.591,27.448 R164.2@96.884,27.155
NetC161_1: C161.1 C163.1 P7.9 R167.2 | length 17.7
  Top Layer w0.381: R167.2@21.936,58.383 24.095,58.383 C163.1@24.134,58.422 24.466,58.09 C161.1@26.293,58.09 27.015,58.09 27.574,57.53 28.144,57.53 28.706,58.092 28.706,64.838 29.529,65.66 30.521,65.66 P7.9@31.5,66.64
NetC161_2: C161.2 C162.1 P7.11 R166.2 | length 17.7
  Top Layer w0.381: R166.2@21.936,56.097 24.095,56.097 C162.1@24.134,56.058 24.466,56.39 C161.2@26.293,56.39 27.015,56.39 27.574,56.95 28.385,56.95 29.287,57.852 29.287,64.597 29.77,65.079 30.521,65.079 P7.11@31.5,64.1
NetC170_1: C170.1 R173.1 R175.2 | length 82.3
  Top Layer w0.305: R173.1@11.981,68.37 11.111,67.5 9.5,67.5 7.246,65.246 7.246,49.616 23.977,32.886 54.814,32.886 55.55,32.15 C170.1@55.55,29.3 55.55,27.362 R175.2@55.36,27.172
NetC170_2: C170.2 R172.1 R174.2 | length 82
  Top Layer w0.305: R172.1@11.981,66.084 11.07,66.995 9.709,66.995 7.751,65.037 7.751,49.825 24.186,33.39 55.21,33.39 57.25,31.35 C170.2@57.25,29.3 57.25,27.372 R174.2@57.45,27.172
NetC171_1: C171.1 C173.1 P7.5 R177.2 | length 11.2
  Top Layer w0.381: R177.2@21.936,68.37 21.975,68.409 C173.1@24.134,68.409 24.466,68.077 C171.1@26.293,68.077 26.4,68.077 29.064,70.74 30.521,70.74 P7.5@31.5,71.72
NetC171_2: C171.2 C172.1 P7.7 R176.2 | length 12.1
  Top Layer w0.381: R176.2@21.936,66.084 24.095,66.084 C172.1@24.134,66.045 24.466,66.377 C171.2@26.293,66.377 28.198,68.282 28.198,69.053 29.305,70.159 30.521,70.159 P7.7@31.5,69.18
NetC180_1: C180.1 R183.1 R185.2 | length 59.1
  Top Layer w0.305: R183.1@11.981,78.238 11.255,77.512 9.755,77.512 6.103,73.86 6.103,49.235 16.495,38.843 16.495,29.967 C180.1@15.881,29.353 15.881,27.448 R185.2@15.588,27.155
NetC180_2: C180.2 R182.1 R184.2 | length 58.1
  Top Layer w0.305: R182.1@11.981,76.079 11.248,76.812 9.904,76.812 6.608,73.516 6.608,49.444 17,39.052 17,29.934 C180.2@17.581,29.353 17.581,27.448 R184.2@17.874,27.155
NetC181_1: C181.1 C183.1 P7.1 R187.2 | length 11.1
  Top Layer w0.4: R187.2@21.936,78.238 23.968,78.238 C183.1@24.134,78.404 24.466,78.072 C181.1@26.293,78.072 27.379,78.072 29.579,75.872 30.572,75.872 P7.1@31.5,76.8
NetC181_2: C181.2 C182.1 P7.3 R186.2 | length 10.6
  Top Layer w0.381: R186.2@21.936,76.079 24.095,76.079 C182.1@24.134,76.04 24.466,76.372 C181.2@26.293,76.372 28.244,76.372 29.478,75.138 30.622,75.138 P7.3@31.5,74.26
NetC232_1: C232.1 R130.1 R132.2 R136.1 | length 6.6
  Top Layer w0.381: R132.2@13.719,85.803 20.147,85.803 R136.1@20.274,85.676
NetC233_2: C233.2 R131.1 R133.2 R137.1 | length 6.6
  Top Layer w0.381: R133.2@13.719,87.962 18.042,87.962 R137.1@20.274,87.962
NetC234_1: C234.1 R140.1 R142.2 R146.1 | length 6.6
  Top Layer w0.381: R142.2@13.719,95.69 18.042,95.69 R146.1@20.274,95.69
NetC235_2: C235.2 R141.1 R143.2 R147.1 | length 6.6
  Top Layer w0.381: R143.2@13.719,97.976 18.042,97.976 R147.1@20.274,97.976
NetC236_1: C236.1 R150.1 R152.2 R156.1 | length 6.6
  Top Layer w0.381: R152.2@13.719,105.731 18.042,105.731 R156.1@20.274,105.731
NetC237_2: C237.2 R151.1 R153.2 R157.1 | length 6.6
  Top Layer w0.381: R153.2@13.719,108.017 18.042,108.017 R157.1@20.274,108.017
NetC238_1: C238.1 R160.1 R162.2 R166.1 | length 6.6
  Top Layer w0.381: R162.2@13.681,56.097 R166.1@20.236,56.097
NetC239_2: C239.2 R161.1 R163.2 R167.1 | length 6.6
  Top Layer w0.381: R163.2@13.681,58.383 R167.1@20.236,58.383
NetC240_1: C240.1 R170.1 R172.2 R176.1 | length 6.6
  Top Layer w0.381: R172.2@13.681,66.084 R176.1@20.236,66.084
NetC241_2: C241.2 R171.1 R173.2 R177.1 | length 6.6
  Top Layer w0.381: R173.2@13.681,68.37 13.72,68.409 R171.1@15.904,68.409 C241.2@18.004,68.409 18.038,68.409 18.077,68.37 R177.1@20.236,68.37
NetC242_1: C242.1 R180.1 R182.2 R186.1 | length 6.6
  Top Layer w0.4: R182.2@13.681,76.079 18.004,76.079 R186.1@20.236,76.079
NetC243_2: C243.2 R181.1 R183.2 R187.1 | length 6.6
  Top Layer w0.4: R183.2@13.681,78.238 13.72,78.277 R181.1@15.904,78.277 C243.2@18.004,78.277 18.038,78.277 18.077,78.238 R187.1@20.236,78.238
NetCB4_1: CB4.1 U2.5 | length 3.7
  Top Layer w1: CB4.1@124.65,79.7 125.96,79.7 U2.5@127.675,81.415
NetCB7_1: CB7.1 U3.5 | length 5.9
  Top Layer w0.5: U3.5@130.56,91.96 130.56,93.02 131.95,94.41 CB7.1@134.85,94.41
NetD1_2: D1.2 R1.2 R2.1 | length 4.7
  Top Layer w0.4: D1.2@29.574,120.543 29.903,120.214 R1.2@31.86,120.214 R2.1@31.86,122.451
NetD2_2: D2.2 R3.2 R4.1 | length 4.7
  Top Layer w0.4: D2.2@69.579,120.543 69.908,120.214 R3.2@71.865,120.214 R4.1@71.865,122.451
NetD3_2: D3.2 R5.2 R6.1 | length 4.2
  Top Layer w0.4: R6.1@109.584,122.434 R6.1@109.6,122.45 ; D3.2@111.612,120.3 D3.2@111.87,120.558
  Top Layer w0.8: R5.2@109.584,120.543 R6.1@109.584,122.434 ; R5.2@109.65,120.3 D3.2@111.612,120.3
NetD4_2: D4.2 R7.2 R8.1 | length 4.7
  Top Layer w0.4: D4.2@39.337,120.543 39.666,120.214 R7.2@41.623,120.214 R8.1@41.623,122.451
NetD5_2: D5.2 R9.2 R10.1 | length 4.7
  Top Layer w0.4: D5.2@79.342,120.543 81.299,120.543 R9.2@81.628,120.214 R10.1@81.628,122.451
NetD6_2: D6.2 R11.2 R12.1 | length 4.7
  Top Layer w0.3: D6.2@119.347,120.543 119.676,120.214 R11.2@121.633,120.214 R12.1@121.633,122.451
NetD7_2: D7.2 R16.2 R17.1 | length 4.7
  Top Layer w0.4: R17.1@117.823,27.155 R16.2@117.823,29.392 119.78,29.392 D7.2@120.109,29.063
NetD8_2: D8.2 R18.2 R19.1 | length 4.1
  Top Layer w0.6: D8.2@77.458,29.3 R18.2@79.45,29.3 ; R19.1@79.4,27.15 R18.2@79.4,29.25
NetD9_2: D9.2 R20.2 R21.1 | length 4.7
  Top Layer w0.305: D9.2@37.686,29.392 39.643,29.392 R20.2@39.972,29.063 ; R21.1@39.986,27.155 R20.2@39.986,29.392
NetD10_2: D10.2 R22.2 R23.1 | length 4.7
  Top Layer w0.6: R23.1@107.409,27.155 R22.2@107.409,29.392 107.738,29.063 D10.2@109.695,29.063
NetD11_2: D11.2 R24.2 R25.1 | length 4.1
  Top Layer w0.4: D11.2@67.958,29.2 R24.2@69.985,29.2 ; R25.1@69.985,27.155 R24.2@69.985,29.2 ; R24.2@70.05,29.2 R24.2@69.985,29.2
NetD12_2: D12.2 R26.2 R27.1 | length 4.7
  Top Layer w0.305: D12.2@27.907,29.392 R26.2@29.864,29.392 ; R26.2@30.164,29.392 R26.2@30.493,29.063 ; R27.1@30.207,27.155 R26.2@30.207,29.392
NetF1_1: F1.1 VBAT.1
  other v1: 148.1,28.6 141.2,29.3 145.9,30.6 148.2,30.6 143.4,32.2 141.2,32.3 148.1,34.5 141.2,34.9 148.3,37.056 141.7,37.07 145.9,37.1 141.9,39.7 148.1,40.1 141.698,43.044 144.8,43.1 148,43.1
NetP4_2: P4.2 R68.1 | length 4.4
  Top Layer w0.5: P4.2@58.978,104.648 59.156,104.47 59.766,105.08 R68.1@63.08,105.08
NetR31_2: R31.2 R32.2 S3.1 | length 5.7
  Top Layer w0.8: R31.2@117.31,100.75 R32.2@119.51,100.75 119.51,102.797 S3.1@120.503,103.79
NetR33_2: R33.2 R37.2 S4.1 | length 5.6
  Top Layer w0.8: R37.2@126.15,100.75 R33.2@128.29,100.75 128.29,102.703 S4.1@129.377,103.79
NetR38_2: R38.2 R39.2 S5.1 | length 5.7
  Top Layer w0.8: R38.2@135.07,100.75 R39.2@137.35,100.75 137.35,102.89 S5.1@138.25,103.79
NetR57_2: R57.2 U18.4 | length 16.7
  Top Layer w0.6: R57.2@121.548,58.755 121.37,58.577 121.37,52.93 122,52.3 125,52.3 125.7,53 125.7,57.17 126.23,57.7 U18.4@127.244,57.7
NetR58_2: R58.2 R59.1 U18.3 | length 6.1
  Top Layer w0.6: R59.1@123.961,55.983 R58.2@123.961,58.655 124.276,58.97 U18.3@127.244,58.97
NetR61_2: R61.2 R77.2 S1.1 | length 5.7
  Top Layer w0.8: R61.2@108.44,100.75 R77.2@110.65,100.75 110.65,102.81 S1.1@111.63,103.79
NetR66_2: R66.2 S2.1 | length 4.9
  Top Layer w0.8: R66.2@93.8,105.25 97.85,105.25 S2.1@98.45,105.85
NetR440_1: R440.1 R441.2 R442.2 | length 5.1
  Top Layer w0.381: R442.2@51.926,51.22 51.965,51.181 R440.1@54.466,51.181 R441.2@54.466,53.721
PX0_U: C13.2 C81.2 CHIP.38 Q9.3 Q12.2 U12.1 | length 198
  Top Layer w0.2: CHIP.38@69.333,80.247 75.273,80.247 76.11,79.41 78.98,79.41 C13.2@80.124,80.554
  Top Layer w0.4: 34.536,15.764 32.9,17.4 32.9,24.7 35.355,27.155 C81.2@35.527,27.155 35.527,30.473 v1(35.5,30.5) ; v1(35.5,36.9) 41.42,36.9 42.22,37.7 67,37.7 68.4,36.3 105.95,36.3 111.173,41.523 111.173,69.477 102.583,78.067 v1(85.8,78.067) ; C13.2@80.124,80.554 v1(81.699,78.98)
  Top Layer w1: Q12.2@25.748,18.304 29.724,18.304 v1(29.9,18.128) 32.264,15.764 ; U12.1@30,6.5 30,13.5 32.264,15.764 ; Q9.3@35.527,15.764 34.536,15.764 32.264,15.764
  Bottom Layer w0.4: v1(35.5,30.5) v1(35.5,36.9) ; v1(81.699,78.98) 83.53,78.98 84.443,78.067 v1(85.8,78.067)
  other v1: 25.3,3 37.4,3 31.2,3.1 28.1,4.2 34.3,4.5 37.3,5.2 25,6.9 31.1,7.3 35.7,7.5 33.2,7.8 37.3,8.8 25.2,9.5 31.9,9.6 29.5,9.9 35.7,10.1 27.6,10.6 34.1,11.3 29.5,11.7 32.2,13.3 35.5,14 29.9,14.7 33.9,15.8 31.9,16.8 27.5,18.2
